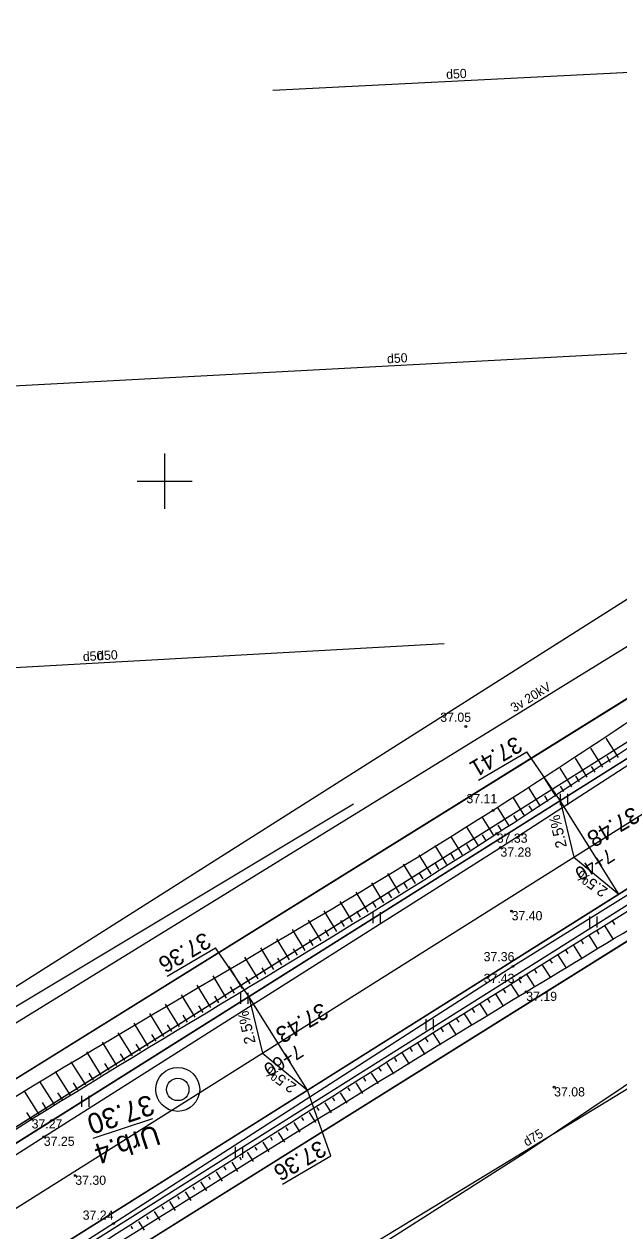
# Model space of a CAD drawing. Extents: x 469981 to 472086, y 246785 to 247785.
# Drawn here: x 471292.4 to 471324.7, y 247309.2 to 247374.8 of the extents above; entities that cross this region are included whole.
import ezdxf

# ---------------------------------------------------------------- set-up
doc = ezdxf.new("R2010")
doc.units = 0
for name, color, linetype in [('0_922', 7, 'Continuous'), ('0_Asfalta_mala', 7, 'Continuous'), ('0_Asfalta_Nomale', 7, 'Continuous'), ('0_Ruut_Braukt', 7, 'Continuous'), ('0_Ruut_nomale', 7, 'Continuous'), ('0_Urbumi5', 7, 'Continuous'), ('0_vertikals', 7, 'Continuous'), ('0_vertkals_cipari', 7, 'Continuous'), ('21', 7, 'Continuous'), ('6_piketaza', 7, 'Continuous'), ('CELI_CMAL_####_####_#', 7, 'Continuous'), ('Default', 7, 'Continuous'), ('DREN_VADP_####_####_#', 7, 'Continuous'), ('DREN_VADP_####_TKST_#', 7, 'Continuous'), ('DREN_VADP_KLKT_####_#', 7, 'Continuous'), ('DREN_VADP_KLKT_TKST_#', 7, 'Continuous'), ('ELEK_VADV_VSPR_####_#', 7, 'Continuous'), ('ELEK_VADV_VSPR_TKST_#', 7, 'Continuous'), ('GEOD_ELEM_####_####_#', 7, 'Continuous'), ('RAMI_UZMR_####_####_#', 7, 'Continuous'), ('RELJ_AATZ_####_TKST_#', 7, 'Continuous'), ('RELJ_ELEM_####_####_#', 7, 'Continuous'), ('RELJ_NOGA_####_####_#', 7, 'Continuous'), ('RELJ_NOGL_####_####_#', 7, 'Continuous'), ('ROBZ_IERR_####_####_#', 7, 'Continuous'), ('ROBZ_PROJ_####_####_#', 7, 'Continuous'), ('TERT_ELEM_####_####_#', 7, 'Continuous'), ('zogi', 7, 'Continuous')]:
    doc.layers.add(name, color=color, linetype=linetype)

# ---------------------------------------------------------------- blocks, each defined once
blk = doc.blocks.new('A$C03B17208')
at = {"layer": 'Default'}
blk.add_circle((1.418, 1.418), 0.723, dxfattribs=at)
at = {"layer": 'zogi'}
blk.add_circle((1.418, 1.418), 1.418, dxfattribs=at)

msp = doc.modelspace()

# ---------------------------------------------------------------- linework, layer by layer
at = {"layer": '0_922'}
msp.add_line((471337.911, 247339.41), (471145.574, 247218.36), dxfattribs=at)
at = {"layer": '0_Asfalta_mala'}
for p, q in [((471336.304, 247341.944), (471143.977, 247220.899)), ((471339.517, 247336.876), (471147.172, 247215.821))]:
    msp.add_line(p, q, dxfattribs=at)
at = {"layer": '0_Asfalta_Nomale'}
for p, q in [((471335.903, 247342.577), (471143.577, 247221.534)), ((471339.918, 247336.243), (471147.572, 247215.187))]:
    msp.add_line(p, q, dxfattribs=at)
at = {"layer": '0_Ruut_Braukt'}
for p, q in [((471336.304, 247341.944), (471143.977, 247220.899)), ((471147.172, 247215.821), (471339.517, 247336.876))]:
    msp.add_line(p, q, dxfattribs=at)
at = {"layer": '0_Ruut_nomale'}
for points in [[(471512.083, 247454.162), (471511.838, 247454.895), (471453.013, 247417.341), (471348.58, 247350.671), (471335.903, 247342.577), (471306.296, 247323.944), (471248.242, 247287.407), (471208.75, 247262.551), (471208.786, 247261.688), (471290.39, 247313.047), (471335.822, 247341.64), (471349.818, 247350.571), (471398.518, 247381.661), (471437.5, 247406.548), (471498.795, 247445.679), (471511.425, 247453.742)], [(471514.294, 247447.566), (471399.037, 247373.985), (471385.85, 247365.566), (471340.791, 247336.792), (471211.253, 247255.265), (471209.116, 247253.92), (471209.079, 247254.783), (471296.254, 247309.648), (471339.517, 247336.876), (471350.75, 247344.048), (471392.723, 247370.844), (471426.479, 247392.394), (471514.049, 247448.299)]]:
    msp.add_lwpolyline(points, close=True, dxfattribs=at)
at = {"layer": '0_Urbumi5'}
msp.add_lwpolyline([(471299.335, 247315.333), (471296.099, 247314.268)], dxfattribs=at)
at = {"layer": '0_vertikals'}
for p, q in [((471317.064, 247333.75), (471319.695, 247335.285)), ((471321.505, 247332.63), (471319.695, 247335.285)), ((471300.137, 247323.097), (471302.769, 247324.631)), ((471304.579, 247321.977), (471302.769, 247324.631)), ((471309.035, 247313.319), (471307.775, 247316.899)), ((471306.404, 247311.784), (471309.035, 247313.319))]:
    msp.add_line(p, q, dxfattribs=at)
for points in [[(471321.505, 247332.63), (471322.257, 247329.558), (471324.701, 247327.552)], [(471304.579, 247321.977), (471305.33, 247318.905), (471307.775, 247316.899)]]:
    msp.add_lwpolyline(points, close=True, dxfattribs=at)
at = {"layer": '21'}
msp.add_line((471337.911, 247339.41), (471145.574, 247218.36), dxfattribs=at)
at = {"layer": '6_piketaza'}
for points in [[(471323.237, 247329.879), (471322.97, 247330.302)], [(471306.31, 247319.226), (471306.044, 247319.649)]]:
    msp.add_lwpolyline(points, dxfattribs=at)
at = {"layer": 'CELI_CMAL_####_####_#'}
for points in [[(471014.161, 247188.048), (471038.308, 247191.645), (471077.61, 247195.71), (471090.836, 247197.337), (471096.461, 247198.582), (471117.856, 247206.682), (471130.197, 247213.261), (471151.631, 247225.738), (471175.407, 247239.608), (471196.168, 247252.49), (471217.229, 247265.52), (471244.784, 247283.359), (471266.102, 247296.914), (471293.433, 247314.365), (471318.262, 247330.084), (471336.637, 247341.969), (471339.45, 247343.841), (471340.412, 247346.293), (471340.291, 247349.818), (471339.894, 247353.24), (471336.901, 247360.015), (471333.813, 247367.721)], [(471347.348, 247327.622), (471345.475, 247334.467), (471344.349, 247336.664), (471343.67, 247337.19), (471342.054, 247337.492), (471341.155, 247337.494), (471339.762, 247336.569), (471318.941, 247323.623), (471297.221, 247309.64), (471268.834, 247291.51), (471247.888, 247278.119), (471219.179, 247259.989), (471200.048, 247247.93), (471177.515, 247234.149), (471154.773, 247220.961), (471131.272, 247207.521), (471119.66, 247201.466), (471103.03, 247195.231), (471092.329, 247192.658), (471077.436, 247189.782), (471058.729, 247187.944), (471037.006, 247184.759), (471015.923, 247182.598), (470992.26, 247181.035)]]:
    msp.add_lwpolyline(points, dxfattribs=at)
at = {"layer": 'DREN_VADP_####_####_#'}
for points in [[(471334.998, 247372.699), (471334.284, 247372.664), (471305.886, 247371.238)], [(471336.274, 247357.539), (471290.06, 247355.078)], [(471315.203, 247341.157), (471272.026, 247338.747)], [(471137.599, 247228.901), (471310.269, 247332.452)]]:
    msp.add_lwpolyline(points, dxfattribs=at)
at = {"layer": 'DREN_VADP_KLKT_####_#'}
msp.add_lwpolyline([(471222.566, 247254.545), (471236.742, 247263.171), (471251.107, 247271.912), (471265.735, 247280.811), (471282.069, 247290.749), (471296.434, 247299.489), (471310.919, 247308.304), (471326.918, 247318.037)], dxfattribs=at)
at = {"layer": 'ELEK_VADV_VSPR_####_#'}
msp.add_line((471279.662, 247313.004), (471335.205, 247347.219), dxfattribs=at)
at = {"layer": 'GEOD_ELEM_####_####_#'}
for p, q in [((471300, 247351.5), (471300, 247350)), ((471298.5, 247350), (471300, 247350)), ((471300, 247350), (471300, 247348.5)), ((471300, 247350), (471301.5, 247350))]:
    msp.add_line(p, q, dxfattribs=at)
at = {"layer": 'RAMI_UZMR_####_####_#'}
for points in [[(471010.572, 247199.465), (471044.448, 247201.846), (471094.566, 247205.368), (471219.251, 247279.294), (471287.982, 247320.045), (471329.582, 247346.385), (471332.466, 247352.407), (471329.951, 247358.592), (471331.784, 247361.204), (471339.558, 247364.746), (471343.514, 247360.959), (471346.629, 247357.978), (471355.9, 247363.1), (471457.4, 247429.3)], [(471380.292, 247353.371), (471352.036, 247335.759), (471352.913, 247327.325), (471347.47, 247325.392), (471345.187, 247325.919), (471342.905, 247329.082), (471319.551, 247313.443), (471222.661, 247251.69), (471157.352, 247211.35), (471144.207, 247202.916), (471131.364, 247196.59), (471113.303, 247188.858), (471105.677, 247188.256), (471083.576, 247183.01), (471075.205, 247182.665), (471043.397, 247175.418), (471016.707, 247172.079), (470997.217, 247171.376)]]:
    msp.add_lwpolyline(points, dxfattribs=at)
at = {"layer": 'RELJ_ELEM_####_####_#'}
for centre in [(471316.381, 247336.658), (471317.859, 247332.101), (471318.062, 247330.842), (471318.262, 247330.084), (471318.87, 247326.628), (471318.941, 247323.623), (471319.351, 247322.992), (471319.665, 247322.242), (471321.182, 247317.052), (471292.77, 247315.312), (471293.433, 247314.365), (471295.145, 247312.248), (471297.221, 247309.64)]:
    msp.add_circle(centre, 0.05, dxfattribs=at)
at = {"layer": 'RELJ_NOGA_####_####_#'}
for p, q in [((471324.677, 247334.979), (471324.019, 247336.026)), ((471323.831, 247334.447), (471323.183, 247335.478)), ((471324.254, 247334.713), (471324.058, 247335.025)), ((471322.136, 247333.384), (471321.506, 247334.39)), ((471322.984, 247333.915), (471322.346, 247334.932)), ((471323.407, 247334.181), (471323.214, 247334.488)), ((471321.289, 247332.854), (471320.664, 247333.852)), ((471322.56, 247333.65), (471322.37, 247333.953)), ((471320.441, 247332.324), (471319.82, 247333.318)), ((471321.713, 247333.119), (471321.524, 247333.42)), ((471319.592, 247331.794), (471318.973, 247332.788)), ((471320.865, 247332.589), (471320.678, 247332.887)), ((471317.894, 247330.738), (471317.271, 247331.742)), ((471318.743, 247331.266), (471318.123, 247332.263)), ((471319.168, 247331.53), (471318.982, 247331.828)), ((471320.017, 247332.059), (471319.83, 247332.357)), ((471317.044, 247330.211), (471316.418, 247331.225)), ((471318.319, 247331.002), (471318.132, 247331.302)), ((471316.193, 247329.686), (471315.563, 247330.709)), ((471317.469, 247330.474), (471317.282, 247330.777)), ((471315.341, 247329.163), (471314.706, 247330.196)), ((471316.618, 247329.949), (471316.43, 247330.254)), ((471313.635, 247328.119), (471312.991, 247329.175)), ((471314.488, 247328.641), (471313.849, 247329.684)), ((471314.914, 247328.902), (471314.724, 247329.213)), ((471315.767, 247329.425), (471315.577, 247329.733)), ((471312.781, 247327.599), (471312.131, 247328.666)), ((471314.061, 247328.38), (471313.869, 247328.695)), ((471311.926, 247327.08), (471311.27, 247328.159)), ((471313.208, 247327.859), (471313.014, 247328.178)), ((471310.216, 247326.043), (471309.546, 247327.148)), ((471311.071, 247326.561), (471310.409, 247327.653)), ((471311.499, 247326.82), (471311.301, 247327.146)), ((471312.353, 247327.339), (471312.158, 247327.661)), ((471309.361, 247325.525), (471308.684, 247326.643)), ((471310.644, 247326.302), (471310.444, 247326.631)), ((471308.505, 247325.007), (471307.821, 247326.138)), ((471309.788, 247325.784), (471309.587, 247326.117)), ((471323.901, 247325.862), (471324.37, 247325.113)), ((471324.325, 247326.128), (471324.467, 247325.901)), ((471307.649, 247324.49), (471306.957, 247325.633)), ((471308.933, 247325.266), (471308.729, 247325.603)), ((471323.054, 247325.331), (471323.515, 247324.595)), ((471323.477, 247325.597), (471323.617, 247325.374)), ((471305.938, 247323.454), (471305.231, 247324.623)), ((471306.794, 247323.972), (471306.094, 247325.128)), ((471307.221, 247324.231), (471307.013, 247324.576)), ((471308.077, 247324.748), (471307.871, 247325.09)), ((471321.784, 247324.533), (471321.919, 247324.318)), ((471322.207, 247324.799), (471322.661, 247324.076)), ((471322.63, 247325.065), (471322.768, 247324.847)), ((471305.083, 247322.936), (471304.367, 247324.117)), ((471306.366, 247323.713), (471306.155, 247324.062)), ((471320.938, 247323.999), (471321.071, 247323.788)), ((471321.361, 247324.266), (471321.809, 247323.557)), ((471304.228, 247322.418), (471303.504, 247323.61)), ((471305.51, 247323.195), (471305.297, 247323.548)), ((471320.094, 247323.464), (471320.225, 247323.257)), ((471320.516, 247323.731), (471320.957, 247323.036)), ((471302.519, 247321.379), (471301.779, 247322.592)), ((471303.373, 247321.899), (471302.641, 247323.102)), ((471304.655, 247322.677), (471304.439, 247323.033)), ((471318.828, 247322.659), (471319.255, 247321.988)), ((471319.249, 247322.927), (471319.379, 247322.725)), ((471319.671, 247323.196), (471320.105, 247322.513)), ((471301.665, 247320.858), (471300.918, 247322.081)), ((471302.946, 247321.639), (471302.725, 247322.002)), ((471303.8, 247322.158), (471303.582, 247322.518)), ((471317.984, 247322.122), (471318.404, 247321.463)), ((471318.406, 247322.39), (471318.533, 247322.191)), ((471300.812, 247320.336), (471300.057, 247321.569)), ((471302.092, 247321.118), (471301.869, 247321.484)), ((471316.719, 247321.316), (471316.842, 247321.123)), ((471317.141, 247321.585), (471317.553, 247320.937)), ((471317.562, 247321.853), (471317.687, 247321.657)), ((471299.959, 247319.813), (471299.197, 247321.054)), ((471301.238, 247320.597), (471301.013, 247320.966)), ((471315.875, 247320.779), (471315.996, 247320.59)), ((471316.297, 247321.048), (471316.703, 247320.411)), ((471298.257, 247318.764), (471297.481, 247320.016)), ((471299.108, 247319.289), (471298.339, 247320.537)), ((471299.533, 247319.552), (471299.304, 247319.925)), ((471300.385, 247320.075), (471300.158, 247320.446)), ((471314.61, 247319.974), (471315.002, 247319.357)), ((471315.032, 247320.242), (471315.15, 247320.056)), ((471315.454, 247320.511), (471315.852, 247319.884)), ((471297.407, 247318.236), (471296.626, 247319.494)), ((471298.682, 247319.027), (471298.451, 247319.402)), ((471313.767, 247319.436), (471314.153, 247318.83)), ((471314.188, 247319.705), (471314.305, 247319.522)), ((471296.559, 247317.708), (471295.772, 247318.969)), ((471297.832, 247318.5), (471297.599, 247318.877)), ((471312.501, 247318.63), (471312.615, 247318.453)), ((471312.923, 247318.899), (471313.303, 247318.302)), ((471313.345, 247319.168), (471313.46, 247318.987)), ((471295.711, 247317.177), (471294.918, 247318.439)), ((471296.983, 247317.972), (471296.747, 247318.35)), ((471311.658, 247318.093), (471311.769, 247317.918)), ((471312.08, 247318.362), (471312.454, 247317.775)), ((471294.02, 247316.109), (471293.219, 247317.372)), ((471294.865, 247316.644), (471294.067, 247317.907)), ((471296.135, 247317.442), (471295.898, 247317.821)), ((471310.815, 247317.556), (471310.924, 247317.384)), ((471311.236, 247317.825), (471311.604, 247317.247)), ((471293.176, 247315.572), (471292.373, 247316.832)), ((471294.442, 247316.377), (471294.202, 247316.756)), ((471295.288, 247316.911), (471295.049, 247317.29)), ((471309.549, 247316.75), (471309.906, 247316.19)), ((471309.971, 247317.019), (471310.079, 247316.849)), ((471310.393, 247317.287), (471310.755, 247316.718)), ((471293.598, 247315.841), (471293.357, 247316.219)), ((471308.706, 247316.213), (471309.058, 247315.661)), ((471309.128, 247316.481), (471309.234, 247316.314)), ((471292.755, 247315.303), (471292.513, 247315.68)), ((471307.441, 247315.406), (471307.544, 247315.244)), ((471307.863, 247315.675), (471308.209, 247315.131)), ((471308.284, 247315.944), (471308.389, 247315.78)), ((471306.598, 247314.869), (471306.7, 247314.709)), ((471307.02, 247315.138), (471307.361, 247314.602)), ((471305.333, 247314.063), (471305.665, 247313.542)), ((471305.755, 247314.331), (471305.855, 247314.174)), ((471306.176, 247314.6), (471306.513, 247314.072)), ((471304.49, 247313.525), (471304.817, 247313.012)), ((471304.911, 247313.794), (471305.01, 247313.639)), ((471303.225, 247312.718), (471303.321, 247312.568)), ((471303.647, 247312.987), (471303.97, 247312.481)), ((471304.068, 247313.256), (471304.166, 247313.103)), ((471302.382, 247312.181), (471302.477, 247312.032)), ((471302.804, 247312.45), (471303.122, 247311.95)), ((471301.539, 247311.643), (471301.633, 247311.496)), ((471301.96, 247311.912), (471302.275, 247311.418)), ((471300.274, 247310.836), (471300.582, 247310.355)), ((471300.696, 247311.105), (471300.789, 247310.96)), ((471301.117, 247311.374), (471301.428, 247310.887)), ((471299.431, 247310.299), (471299.735, 247309.822)), ((471299.853, 247310.567), (471299.944, 247310.424)), ((471298.167, 247309.492), (471298.256, 247309.351)), ((471298.588, 247309.761), (471298.889, 247309.29)), ((471299.01, 247310.03), (471299.1, 247309.888))]:
    msp.add_line(p, q, dxfattribs=at)
for points in [[(471170.189, 247238.813), (471187.045, 247248.806), (471216.962, 247266.603), (471244.501, 247283.959), (471265.809, 247297.732), (471292.77, 247315.312), (471318.062, 247330.842), (471332.326, 247339.791), (471337.257, 247343.054), (471338.429, 247344.75), (471338.591, 247346.479)], [(471155.25, 247220.273), (471177.77, 247233.339), (471200.51, 247247.391), (471219.6, 247259.351), (471248.359, 247277.5), (471269.232, 247290.973), (471319.351, 247322.992), (471333.341, 247331.731), (471337.475, 247334.177), (471338.538, 247334.697), (471340.216, 247335.099), (471340.901, 247334.839)]]:
    msp.add_spline(points, degree=3, dxfattribs=at)
at = {"layer": 'RELJ_NOGL_####_####_#'}
for points in [[(471337.22, 247346.431), (471336.644, 247345.408), (471332.13, 247341.491), (471317.859, 247332.101), (471292.129, 247316.676), (471265.206, 247299.186), (471243.601, 247284.946), (471216.311, 247268.677), (471186.292, 247250.183), (471169.475, 247239.793)], [(471155.819, 247219.592), (471177.985, 247232.653), (471201.025, 247246.801), (471219.926, 247258.493), (471248.971, 247276.784), (471269.467, 247290.521), (471319.665, 247322.242), (471333.631, 247330.726), (471337.921, 247333.442), (471339.285, 247334.228), (471340.237, 247334.435), (471340.94, 247334.352)]]:
    msp.add_spline(points, degree=3, dxfattribs=at)
at = {"layer": 'ROBZ_IERR_####_####_#'}
for points in [[(471513.259, 247488.166), (471524.883, 247464.852), (471341.261, 247348.2), (471124.72, 247213.54), (471093.674, 247200.298), (471050.609, 247195.379), (471001.509, 247189.266), (470977.922, 247249.601)], [(471168.816, 247177.651), (471133.176, 247205.05), (471346.741, 247338.478), (471363.107, 247281.069)]]:
    msp.add_lwpolyline(points, dxfattribs=at)
at = {"layer": 'ROBZ_PROJ_####_####_#'}
for points in [[(470613.752, 247179.765), (470688.303, 247197.106), (470783.692, 247219.293), (470809.088, 247224.67), (470845.751, 247226.447), (470876.169, 247225.296), (470921.641, 247209.731), (470967.353, 247194.084), (470989.48, 247188.802), (471001.509, 247189.266), (471050.609, 247195.379), (471093.674, 247200.298), (471124.72, 247213.54), (471341.261, 247348.2), (471524.883, 247464.852)], [(471398.351, 247372.094), (471346.741, 247338.478), (471133.176, 247205.05), (471108.425, 247194.786), (471087.339, 247189.709), (471023.306, 247181.157), (470962.604, 247185.245), (470905.63, 247205.857), (470878.75, 247214.454), (470852.344, 247217.039), (470815.743, 247215.147), (470778.583, 247209.26), (470718.669, 247194.633), (470636.973, 247175.147), (470468.364, 247124.23), (470431.624, 247112.202), (470396.219, 247097.502), (470371.503, 247083.47), (470275.956, 246992.729), (470152.342, 246907.761), (470066.737, 246851.23)]]:
    msp.add_lwpolyline(points, dxfattribs=at)
at = {"layer": 'TERT_ELEM_####_####_#'}
for p, q in [((471321.534, 247332.394), (471321.534, 247332.994)), ((471321.934, 247332.394), (471321.934, 247332.994)), ((471311.337, 247325.962), (471311.337, 247326.562)), ((471311.737, 247325.962), (471311.737, 247326.562)), ((471323.13, 247325.732), (471323.13, 247326.332)), ((471323.53, 247325.732), (471323.53, 247326.332)), ((471304.138, 247321.589), (471304.138, 247322.189)), ((471304.538, 247321.589), (471304.538, 247322.189)), ((471314.218, 247320.158), (471314.218, 247320.758)), ((471314.618, 247320.158), (471314.618, 247320.758)), ((471295.506, 247315.992), (471295.506, 247316.592)), ((471295.906, 247315.992), (471295.906, 247316.592)), ((471303.849, 247313.212), (471303.849, 247313.812)), ((471304.249, 247313.212), (471304.249, 247313.812))]:
    msp.add_line(p, q, dxfattribs=at)

# ---------------------------------------------------------------- block references
at = {"layer": '0_Urbumi5', "xscale": 0.8410063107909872, "yscale": 0.8410063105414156, "rotation": 16.26779999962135}
msp.add_blockref('A$C03B17208', (471299.906, 247315.453), dxfattribs=at)

# ---------------------------------------------------------------- texts
at = {"layer": '0_Urbumi5'}
for s, p in [('37.30', (471299.215, 247316.674)), ('Urb.4', (471299.529, 247315.034))]:
    msp.add_text(s, height=1.11, rotation=198.21642, dxfattribs=at).set_placement(p)
at = {"layer": '0_vertkals_cipari'}
for s, height, rotation, p in [('37.41', 0.9, 210.25073, (471319.098, 247336.17)), ('2.5%', 0.5993, 103.03443, (471321.881, 247330.126)), ('37.48', 0.9, 210.25073, (471325.48, 247332.343)), ('2.5%', 0.5993, 144.2467, (471324.147, 247327.823)), ('37.36', 0.9, 210.25073, (471302.171, 247325.517)), ('37.43', 0.9, 210.25073, (471308.554, 247321.69)), ('2.5%', 0.5993, 103.03443, (471304.954, 247319.473)), ('2.5%', 0.5993, 144.2467, (471307.22, 247317.17)), ('37.36', 0.9, 210.25073, (471308.438, 247314.204))]:
    msp.add_text(s, height=height, rotation=rotation, dxfattribs=at).set_placement(p)
at = {"layer": '6_piketaza'}
for s, p in [('7+40', (471324.149, 247330.07)), ('7+60', (471307.223, 247319.417))]:
    msp.add_text(s, height=0.75, rotation=212.18491, dxfattribs=at).set_placement(p)
at = {"layer": 'DREN_VADP_####_TKST_#'}
for rotation, p in [(2.873, (471315.322, 247371.862)), (3.04849, (471312.107, 247356.403)), (3.1942, (471295.567, 247340.211)), (3.1942, (471296.349, 247340.255))]:
    msp.add_text('d50', height=0.5, rotation=rotation, dxfattribs=at).set_placement(p)
at = {"layer": 'DREN_VADP_KLKT_TKST_#'}
msp.add_text('d75', height=0.5, rotation=31.31672, dxfattribs=at).set_placement((471319.692, 247313.816))
at = {"layer": 'ELEK_VADV_VSPR_TKST_#'}
msp.add_text('3v 20kV', height=0.5, rotation=31.63345, dxfattribs=at).set_placement((471319.006, 247337.417))
at = {"layer": 'RELJ_AATZ_####_TKST_#'}
for s, p in [('37.05', (471314.991, 247336.915)), ('37.11', (471316.414, 247332.493)), ('37.33', (471318.062, 247330.342)), ('37.28', (471318.262, 247329.584)), ('37.40', (471318.87, 247326.128)), ('37.36', (471317.348, 247323.9)), ('37.43', (471317.352, 247322.724)), ('37.19', (471319.665, 247321.742)), ('37.08', (471321.182, 247316.552)), ('37.27', (471292.77, 247314.812)), ('37.25', (471293.433, 247313.865)), ('37.30', (471295.145, 247311.748)), ('37.24', (471295.547, 247309.85))]:
    msp.add_text(s, height=0.5, dxfattribs=at).set_placement(p)

doc.saveas('drawing.dxf')
